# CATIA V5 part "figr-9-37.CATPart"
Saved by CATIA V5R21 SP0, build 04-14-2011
Part number: Part1
Bounding box of the stored display mesh (mm): x 0 to 200, y -70 to 70, z -70 to 70
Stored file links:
  D:\CATIA V5R21 E-RESOURCES\CATIA-V5R21\catia-v5r21-prt\c09-catia-v5r20-prt\c09-catia-v5r21-figr-9-37.CATPart
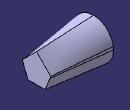
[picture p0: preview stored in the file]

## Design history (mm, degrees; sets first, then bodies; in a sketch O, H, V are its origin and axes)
Set1
  Plane1: type Offset, RefPlane yz-plane, Offset 200
Body1 (main body)
  Sketch1 on yz-plane, origin (0, 0, 0), H (0, 1, 0), V (0, 0, 1)
    circle A1 centre (0, 0) radius 70
    point P1 (70, 0)
    point P2 (-48.9898, -50)
    point P3 (48.9898, -50)
    point P4 (69.282, 10)
    point P5 (-69.282, 10)
    point P6 (0, 70)
    radius A1 = 70
    coincidence: A1 P1, P1 H, P2 A1, P3 A1, P4 A1, P5 A1, P6 V
  Sketch2 on Plane1, origin (200, 0, 0), H (0, 1, 0), V (0, 0, 1)
    point P1 (-30, -40)
    line L1 (-30, -40) -> (30, -40)
    point P2 (30, -40)
    line L2 (30, -40) -> (50, 10)
    point P3 (50, 10)
    line L3 (50, 10) -> (0, 60)
    point P4 (0, 60)
    line L4 (0, 60) -> (-50, 10)
    point P5 (-50, 10)
    line L5 (-50, 10) -> (-30, -40)
    horizontal: L1 H
    coincidence: P4 V
    symmetry: P3 P5 V, P2 P1 V
  Loft1: Sections (edge of Sketch1; Sketch2), SectionCouplingPoints ({coupling CouplingPoints (vertex of Sketch1; vertex [element of Sketch2 | element of Sketch2])}; {coupling CouplingPoints (vertex of Sketch1; vertex [element of Sketch2 | element of Sketch2])}; {coupling CouplingPoints (vertex of Sketch1; vertex [element of Sketch2 | element of Sketch2])}; {coupling CouplingPoints (vertex of Sketch1; vertex [element of Sketch2 | element of Sketch2])})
